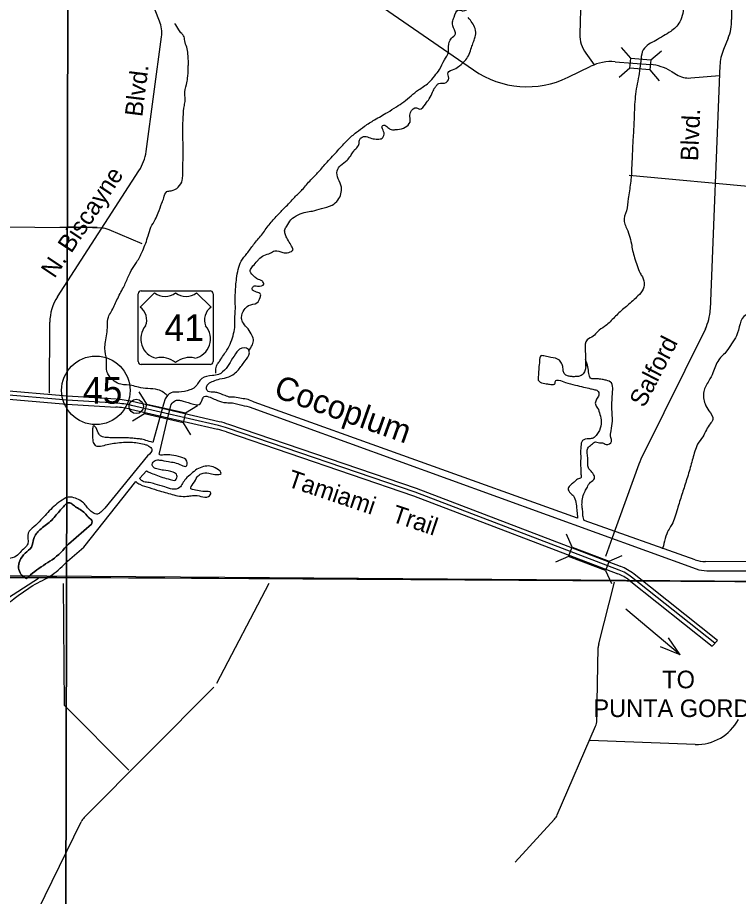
# Model space of a CAD drawing. Extents: x 408847 to 817539, y 923858 to 1151780.
# Drawn here: x 573593 to 592003, y 973182 to 995634 of the extents above; entities that cross this region are included whole.
import ezdxf

# ---------------------------------------------------------------- set-up
doc = ezdxf.new("R2010")
doc.units = 0
for name, color, linetype in [('Adjacent County and State Text', 7, 'Continuous'), ('Bridges', 7, 'Continuous'), ('Cities Incorporated Area', 7, 'Continuous'), ('Cities Incorporated Linear Boundaries', 7, 'Continuous'), ('County Boundary', 7, 'Continuous'), ('Lakes and Ponds', 7, 'Continuous'), ('Level 10', 7, 'Continuous'), ('Level 12', 7, 'Continuous'), ('Level 2', 7, 'Continuous'), ('Level 42', 7, 'Continuous'), ('Level 6', 7, 'Continuous'), ('Local Roads Related Text', 7, 'Continuous'), ('Masks for Road Features', 7, 'Continuous'), ('Narrow River Creek and Branch and Slough', 7, 'Continuous'), ('Other Incorporated Names', 7, 'Continuous'), ('Planning Number US Highways', 7, 'Continuous'), ('Quad Borders', 7, 'Continuous'), ('Roadshields US Highways', 7, 'Continuous'), ('State Roads Related Text', 7, 'Continuous'), ('Town Centers', 7, 'Continuous'), ('US Highways Related Text', 7, 'Continuous'), ('US Routes Highway Center Lines', 7, 'Continuous')]:
    doc.layers.add(name, color=color, linetype=linetype)

msp = doc.modelspace()

# ---------------------------------------------------------------- linework, layer by layer
at = {"layer": 'Adjacent County and State Text'}
msp.add_line((575477, 982694), (574892, 982185), dxfattribs=at)
for points in [[(573818, 981306), (573679, 981416), (573619, 981572), (573648, 981758), (573787, 981950), (573945, 982107), (574004, 982323), (574163, 982547), (574433, 982766), (574664, 983027), (574862, 983240)], [(574862, 983240), (574924, 983236), (575022, 983175), (575127, 983105), (575251, 983022), (575360, 982915), (575408, 982858), (575485, 982788), (575493, 982722), (575477, 982694)], [(574892, 982185), (574475, 981781), (574251, 981640), (573818, 981306)]]:
    msp.add_spline(points, degree=3, dxfattribs=at)
at = {"layer": 'Bridges'}
for p, q in [((589253, 994593), (589018, 994869)), ((589763, 994552), (590039, 994786)), ((589232, 994338), (588956, 994104)), ((589742, 994297), (589977, 994021)), ((576891, 985761), (576699, 986069)), ((577877, 985532), (578184, 985724)), ((576833, 985512), (576526, 985321)), ((577819, 985283), (578010, 984976)), ((587757, 982108), (587609, 982438)), ((587666, 981868), (587335, 981721)), ((588702, 981746), (589033, 981894)), ((588611, 981507), (588758, 981176))]:
    msp.add_line(p, q, dxfattribs=at)
for points in [[(589253, 994593), (589763, 994552), (589742, 994297), (589232, 994338)], [(576891, 985761), (577877, 985532), (577819, 985283), (576833, 985512)], [(587757, 982108), (588702, 981746), (588611, 981507), (587666, 981868)]]:
    msp.add_lwpolyline(points, close=True, dxfattribs=at)
at = {"layer": 'Cities Incorporated Area'}
msp.add_line((573206, 981335), (615530, 981117), dxfattribs=at)
at = {"layer": 'Cities Incorporated Linear Boundaries'}
msp.add_lwpolyline([(567137, 973534), (573183, 973447), (573204, 981332), (576741, 981321), (637423, 980943), (637436, 1005786)], dxfattribs=at)
at = {"layer": 'County Boundary'}
msp.add_line((573205, 981378), (642276, 980861), dxfattribs=at)
at = {"layer": 'Lakes and Ponds'}
for p, q in [((577360, 985897), (577321, 985757)), ((577321, 985757), (577236, 985455)), ((577434, 985413), (577507, 985717)), ((577507, 985717), (577515, 985752)), ((579510, 985689), (590923, 981549)), ((587892, 982842), (579635, 985807)), ((577236, 985455), (577046, 984782)), ((577215, 984506), (577434, 985413)), ((576912, 984439), (575821, 983103)), ((576713, 983866), (576881, 984053)), ((575282, 982106), (576613, 983778)), ((590900, 981781), (588059, 982782)), ((574892, 982185), (575477, 982694)), ((575477, 982694), (574892, 982185)), ((574871, 981748), (575282, 982106)), ((615499, 981594), (591161, 981736)), ((591193, 981501), (615555, 981401))]:
    msp.add_line(p, q, dxfattribs=at)
for centre, start, end in [((591166, 982536), 250.5958, 269.6668), ((591196, 982301), 250.0599, 269.7653)]:
    msp.add_arc(centre, 800, start, end, dxfattribs=at)
for points in [[(579635, 985807), (579479, 985874), (579311, 985905), (579133, 985934), (579037, 985935), (578890, 985976), (578682, 986053), (578574, 986064), (578434, 986105), (578419, 986195), (578469, 986281), (578592, 986346), (578762, 986403), (578987, 986454), (579234, 986638), (579398, 986856), (579512, 987069), (579486, 987156), (579264, 987161), (579196, 987093), (579050, 986872), (578918, 986670), (578725, 986517), (578567, 986486), (578296, 986414), (578119, 986191), (577992, 986123), (577710, 986065), (577511, 986048), (577360, 985897)], [(588100, 986895), (588068, 986584), (587988, 986489), (587889, 986465), (587777, 986460), (587683, 986472), (587598, 986499), (587542, 986563), (587525, 986664), (587499, 986772), (587432, 986878), (587211, 986954), (587067, 986983), (586955, 986990), (586924, 986864), (586904, 986675), (586893, 986499), (586892, 986375), (586936, 986323), (587096, 986280), (587208, 986261), (587298, 986268), (587312, 986278), (587328, 986346), (587411, 986370), (587584, 986313), (587842, 986245), (588050, 986196), (588225, 986153), (588339, 986128), (588421, 986085), (588426, 985959), (588367, 985859), (588351, 985755), (588404, 985659), (588467, 985496), (588500, 985308), (588452, 985088), (588389, 984984), (588295, 984892), (588184, 984873), (588020, 984826), (587979, 984674), (587972, 984554), (587975, 984402), (587970, 984243), (587977, 984103), (587982, 983967), (587985, 983885), (587895, 983845), (587806, 983764), (587716, 983692), (587655, 983604), (587712, 983486), (587788, 983415), (587849, 983253), (587874, 983062), (587890, 982896), (587892, 982842)], [(588059, 982782), (588033, 982909), (588022, 983057), (588008, 983164), (588015, 983300), (588054, 983464), (588085, 983534), (588144, 983639), (588223, 983761), (588329, 983859), (588302, 983961), (588219, 984068), (588161, 984156), (588154, 984254), (588157, 984380), (588159, 984637), (588247, 984726), (588350, 984792), (588494, 984767), (588530, 984769), (588622, 984728), (588762, 984803), (588743, 984906), (588752, 985080), (588786, 985322), (588772, 985634), (588771, 985749), (588780, 985963), (588791, 986121), (588761, 986299), (588627, 986368), (588519, 986391), (588395, 986404), (588227, 986423), (588182, 986537), (588159, 986708), (588100, 986895)], [(577515, 985752), (577628, 985849), (577728, 985857), (577818, 985838), (578088, 985754), (578230, 985749), (578308, 985865), (578359, 985951), (578509, 985934), (578649, 985873), (578858, 985804), (578996, 985795), (579114, 985786), (579252, 985749), (579510, 985689)], [(577046, 984782), (576868, 984832), (576729, 984867), (576675, 984872), (576537, 984888), (576385, 984895), (576211, 984896), (576032, 984896), (575870, 984907), (575729, 984937), (575673, 984990), (575596, 985151), (575536, 985203), (575510, 985125), (575509, 984957), (575516, 984815), (575575, 984704), (575757, 984695), (575921, 984736), (576096, 984765), (576298, 984784), (576524, 984784), (576700, 984763), (576866, 984722), (576947, 984686), (577023, 984607), (576912, 984439)], [(576881, 984053), (576967, 984013), (577122, 983951), (577298, 983886), (577486, 983833), (577622, 983820), (577661, 983938), (577569, 984019), (577317, 984068), (577179, 984095), (577064, 984146), (577030, 984220), (577109, 984320), (577217, 984331), (577443, 984292), (577603, 984265), (577780, 984198), (577900, 984171), (577915, 984303), (577764, 984404), (577522, 984458), (577328, 984461), (577212, 984476), (577215, 984506)], [(576613, 983778), (576716, 983710), (576952, 983626), (577220, 983542), (577405, 983491), (577585, 983438), (577965, 983408), (578087, 983423), (578277, 983402), (578469, 983396), (578532, 983488), (578324, 983526), (578136, 983561), (578014, 983598), (578081, 983727), (578183, 983901), (578281, 983982), (578475, 983999), (578633, 983960), (578791, 983985), (578682, 984108), (578340, 984162), (578174, 984095), (578027, 983978), (577886, 983851), (577807, 983733), (577730, 983627), (577544, 983588), (577352, 983646), (577105, 983715), (576953, 983756), (576819, 983775), (576743, 983826), (576713, 983866)], [(574828, 983368), (574641, 983243), (574329, 982952), (574190, 982799), (574011, 982624), (573864, 982465), (573852, 982192), (573655, 981972), (573514, 981849), (573286, 981763), (573264, 981701), (573256, 981557), (573203, 981488), (572924, 981593), (572674, 981642), (572316, 981519), (572166, 981339), (572213, 981155), (572326, 980964), (572475, 980760), (572554, 980599), (572547, 980536)], [(574862, 983240), (574664, 983027), (574433, 982766), (574163, 982547), (574004, 982323), (573945, 982107), (573787, 981950), (573648, 981758), (573619, 981572), (573679, 981416), (573818, 981306)], [(573818, 981306), (573679, 981416), (573619, 981572), (573648, 981758), (573787, 981950), (573945, 982107), (574004, 982323), (574163, 982547), (574433, 982766), (574664, 983027), (574862, 983240)], [(575821, 983103), (575717, 982995), (575631, 982951), (575525, 982978), (575421, 983063), (575342, 983163), (575251, 983258), (575109, 983339), (574947, 983382), (574828, 983368)], [(575477, 982694), (575493, 982722), (575485, 982788), (575408, 982858), (575360, 982915), (575251, 983022), (575127, 983105), (575022, 983175), (574924, 983236), (574862, 983240)], [(574862, 983240), (574924, 983236), (575022, 983175), (575127, 983105), (575251, 983022), (575360, 982915), (575408, 982858), (575485, 982788), (575493, 982722), (575477, 982694)], [(573818, 981306), (574251, 981640), (574475, 981781), (574892, 982185)], [(574892, 982185), (574475, 981781), (574251, 981640), (573818, 981306)], [(567912, 978885), (568329, 978962), (568739, 978950), (569120, 978879), (569537, 978739), (569871, 978696), (570275, 978881), (570893, 979103), (571420, 979348), (571833, 979689), (572016, 979821), (573025, 980438), (573444, 980744), (573983, 981122), (574472, 981399), (574871, 981748)]]:
    msp.add_spline(points, degree=3, dxfattribs=at)
at = {"layer": 'Level 10'}
msp.add_line((615494, 981067), (573213, 981340), dxfattribs=at)
at = {"layer": 'Level 12'}
for p, q in [((589212, 991608), (593732, 991190)), ((573216, 980725), (574131, 981312)), ((578678, 978626), (580016, 981182)), ((588436, 979635), (588834, 981212)), ((574788, 978058), (574766, 981174)), ((588389, 977681), (588423, 979544)), ((575295, 975194), (578607, 978529)), ((576437, 976403), (574788, 978058)), ((587376, 975265), (588356, 977529)), ((590895, 977065), (588211, 977169)), ((586300, 974054), (587304, 975154)), ((574111, 972825), (575219, 975088))]:
    msp.add_line(p, q, dxfattribs=at)
for centre, radius, start, end in [((588823, 979537), 400, 165.8077, 178.9375), ((587989, 977688), 400, 336.5917, 358.9375), ((590941, 978265), 1200, 267.7972, 332.1984), ((575579, 974913), 400, 135.1954, 153.9033), ((587009, 975424), 400, 317.6167, 336.5918)]:
    msp.add_arc(centre, radius, start, end, dxfattribs=at)
at = {"layer": 'Level 2'}
msp.add_line((615480, 981107), (573213, 981326), dxfattribs=at)
at = {"layer": 'Level 42'}
msp.add_spline([(579493, 987134), (579591, 987273), (579616, 987411), (579559, 987552), (579448, 987719), (579337, 987864), (579314, 987972), (579377, 988168), (579492, 988275), (579705, 988348), (579790, 988482), (579796, 988570), (579697, 988620), (579585, 988701), (579620, 988773), (579718, 988775), (579880, 988824), (579845, 988896), (579717, 988955), (579635, 989021), (579536, 989146), (579573, 989252), (579690, 989384), (579748, 989457), (579883, 989559), (580046, 989618), (580160, 989673), (580368, 989632), (580520, 989633), (580627, 989708), (580591, 989793), (580552, 989863), (580465, 990006), (580427, 990110), (580416, 990214), (580469, 990306), (580572, 990466), (580761, 990595), (580958, 990666), (581122, 990691), (581356, 990755), (581625, 990842), (581774, 990971), (581849, 991135), (581862, 991301), (581784, 991514), (581755, 991720), (581844, 991856), (582007, 991993), (582100, 992103), (582161, 992201), (582228, 992284), (582312, 992392), (582323, 992502), (582366, 992566), (582492, 992595), (582636, 992546), (582788, 992531), (582906, 992554), (582948, 992624), (582927, 992761), (582900, 992863), (582944, 992885), (583052, 992826), (583133, 992773), (583197, 992767), (583237, 992771), (583298, 992774), (583492, 992831), (583615, 992965), (583616, 993067), (583627, 993211), (583784, 993328), (583861, 993296), (584012, 993425), (584107, 993561), (584193, 993728), (584254, 993848), (584296, 993904), (584316, 993934), (584500, 993961), (584605, 994086), (584586, 994231), (584747, 994316), (584880, 994405), (585037, 994552), (585124, 994698), (585187, 994870), (585208, 994930), (585255, 995060), (585289, 995172), (585277, 995352), (585103, 995634)], degree=3, dxfattribs=at)
msp.add_spline([(579493, 987134), (579591, 987273), (579616, 987411), (579559, 987552), (579448, 987719), (579337, 987864), (579314, 987972), (579377, 988168), (579492, 988275), (579705, 988348), (579790, 988482), (579796, 988570), (579697, 988620), (579585, 988701), (579620, 988773), (579718, 988775), (579880, 988824), (579845, 988896), (579717, 988955), (579635, 989021), (579536, 989146), (579573, 989252), (579690, 989384), (579748, 989457), (579883, 989559), (580046, 989618), (580160, 989673), (580368, 989632), (580520, 989633), (580627, 989708), (580591, 989793), (580552, 989863), (580465, 990006), (580427, 990110), (580416, 990214), (580469, 990306), (580572, 990466), (580761, 990595), (580958, 990666), (581122, 990691), (581356, 990755), (581625, 990842), (581774, 990971), (581849, 991135), (581862, 991301), (581784, 991514), (581755, 991720), (581844, 991856), (582007, 991993), (582100, 992103), (582161, 992201), (582228, 992284), (582312, 992392), (582323, 992502), (582366, 992566), (582492, 992595), (582636, 992546), (582788, 992531), (582906, 992554), (582948, 992624), (582927, 992761), (582900, 992863), (582944, 992885), (583052, 992826), (583133, 992773), (583197, 992767), (583237, 992771), (583298, 992774), (583492, 992831), (583615, 992965), (583616, 993067), (583627, 993211), (583784, 993328), (583861, 993296), (584012, 993425), (584107, 993561), (584193, 993728), (584254, 993848), (584296, 993904), (584316, 993934), (584500, 993961), (584605, 994086), (584586, 994231), (584747, 994316), (584880, 994405), (585037, 994552), (585124, 994698), (585187, 994870), (585208, 994930), (585255, 995060), (585289, 995172), (585277, 995352), (585103, 995634)], degree=3, dxfattribs=at)
at = {"layer": 'Level 6'}
for p, q in [((574859, 985960), (563605, 986924)), ((563588, 986725), (574854, 985760)), ((576112, 985884), (574859, 985960)), ((574854, 985760), (576099, 985684)), ((578744, 985309), (576523, 985824)), ((576478, 985629), (578699, 985115)), ((583779, 983599), (578990, 985239)), ((578925, 985050), (583703, 983414)), ((588995, 981612), (583779, 983599)), ((583703, 983414), (588924, 981425)), ((591467, 979721), (589336, 981417)), ((589212, 981260), (591334, 979579)), ((591334, 979579), (591467, 979721))]:
    msp.add_line(p, q, dxfattribs=at)
for centre, radius, start, end in [((575959, 983388), 2300, 76.9617, 86.4971), ((575959, 983388), 2500, 76.9618, 86.4971), ((578180, 982874), 2500, 71.0986, 76.9617), ((578180, 982874), 2300, 71.0986, 76.9617), ((588527, 980397), 1102, 51.5584, 68.8901), ((588526, 980395), 1304, 51.5646, 68.8963)]:
    msp.add_arc(centre, radius, start, end, dxfattribs=at)
at = {"layer": 'Masks for Road Features'}
msp.add_line((574673, 990280), (575626, 990280), dxfattribs=at)
at = {"layer": 'Narrow River Creek and Branch and Slough'}
for p, q in [((574849, 990261), (573215, 990277)), ((575722, 990257), (574876, 990292)), ((576776, 989852), (575930, 990210))]:
    msp.add_line(p, q, dxfattribs=at)
msp.add_arc((575697, 989657), 600, 67.0757, 87.5696, dxfattribs=at)
for points in [[(600169, 1012784), (600058, 1012638), (599920, 1012443), (599719, 1012088), (599450, 1011673), (599276, 1011347), (599058, 1011038), (598896, 1010777), (598739, 1010409), (598657, 1010153), (598647, 1009855), (598678, 1009338), (598785, 1008977), (598903, 1008686), (598947, 1008369), (598905, 1008135), (598771, 1007855), (598593, 1007524), (598441, 1007206), (598417, 1007004), (598483, 1006701), (598554, 1006529), (598534, 1006321), (598389, 1006107), (598209, 1005836), (597997, 1005653), (597777, 1005618), (597548, 1005483), (597478, 1005151), (597508, 1004705), (597499, 1004456), (597478, 1004110), (597477, 1003653), (597501, 1003371), (597506, 1003156), (597390, 1002939), (597285, 1002773), (597271, 1002525), (597245, 1002295), (597200, 1002141), (597119, 1001921), (597021, 1001749), (596899, 1001652), (596587, 1001465), (596394, 1001342), (596219, 1001217), (595523, 1000641), (595291, 1000412), (595060, 1000227), (594814, 1000032), (594679, 999841), (594593, 999511), (594546, 999119), (594524, 998854), (594515, 998169), (594528, 997456), (594514, 997152), (594502, 996870), (594422, 996634), (594317, 996436), (594097, 996133), (593908, 995860), (593793, 995594), (593754, 995166), (593746, 994709), (593725, 994196), (593704, 993810), (593743, 993377), (593920, 992968), (594024, 992602), (594067, 992266), (593924, 991872), (593854, 991542), (593700, 990982), (593552, 990640), (593421, 990281), (593362, 990075), (593242, 989855), (593098, 989654), (592947, 989424), (592821, 989113), (592715, 988849), (592593, 988597), (592471, 988344), (592389, 988122), (592197, 988037), (591955, 987504), (591829, 987302), (591702, 987111), (591500, 986888), (591352, 986562), (591246, 986352), (591118, 986081), (591150, 985764), (591249, 985589), (591351, 985364), (591277, 985259)], [(590739, 997053), (590710, 996823), (590659, 996505), (590630, 996254), (590612, 995968), (590584, 995740), (590504, 995528), (590397, 995381), (590273, 995279), (590086, 995164), (589891, 995049), (589718, 994952), (589571, 994811), (589515, 994581), (589484, 994339), (589446, 994079), (589394, 993811), (589346, 993284), (589334, 992956), (589309, 992519), (589290, 992107), (589276, 991786), (589247, 991404), (589188, 991008), (589140, 990698), (589084, 990423), (589131, 990291), (589268, 989856), (589301, 989685), (589414, 989302), (589495, 989105), (589550, 989009), (589589, 988906), (589566, 988698), (589435, 988523), (589173, 988282), (589042, 988172), (588808, 987948), (588581, 987739), (588410, 987616), (588297, 987496), (588138, 987401), (588088, 987161), (588101, 986934), (588095, 986718)], [(578655, 986548), (578656, 986662), (578699, 986784), (578762, 986868), (578853, 987013), (578940, 987137), (579041, 987345), (579109, 987561), (579140, 987769), (579137, 987919), (579157, 988205), (579152, 988337), (579156, 988608), (579185, 988968), (579228, 989202), (579304, 989412), (579449, 989605), (579619, 989835), (579819, 990078), (580019, 990343), (580221, 990578), (580420, 990779), (580670, 991044), (580864, 991241), (581081, 991488), (581281, 991695), (581497, 991942), (581769, 992235), (582025, 992508), (582246, 992705), (582452, 992856), (582711, 993022), (583040, 993213), (583266, 993353), (583455, 993482), (583646, 993638), (583831, 993785), (584088, 993969), (584246, 994145), (584369, 994310), (584493, 994552), (584596, 994751), (584599, 994895), (584671, 995105), (584773, 995217), (584748, 995323), (584704, 995524), (584742, 995646), (584854, 995829), (584974, 995805), (585132, 995907)], [(577407, 985989), (577321, 986055), (577176, 986128), (576918, 986154), (576678, 986189), (576514, 986233), (576230, 986266), (575932, 986480), (575876, 986591), (575860, 986890), (575822, 987182), (575840, 987350), (575889, 987761), (575912, 987977), (575983, 988115), (576129, 988420), (576296, 988742), (576418, 989007), (576527, 989223), (576659, 989426), (576789, 989682), (576927, 990062), (576997, 990277), (577110, 990475), (577183, 990643), (577279, 990897), (577326, 991025), (577405, 991188), (577514, 991210), (577696, 991303), (577800, 991480), (577809, 991616), (577815, 991927), (577825, 992187), (577818, 992432), (577811, 992768), (577825, 993090), (577853, 993391), (577874, 993523), (577861, 993675), (577903, 993923), (577936, 994089), (577950, 994333), (577955, 994462), (577942, 994710), (577912, 994876), (577863, 995041), (577834, 995167), (577784, 995224), (577709, 995322), (577612, 995487)], [(591277, 985259), (591184, 985101), (591090, 984925), (590961, 984734), (590888, 984554), (590787, 984184), (590670, 983800), (590558, 983446), (590443, 983083), (590304, 982687), (590152, 982389), (590058, 982083), (590058, 982085)]]:
    msp.add_spline(points, degree=3, dxfattribs=at)
at = {"layer": 'Other Incorporated Names'}
for p, q in [((588057, 999550), (587954, 995209)), ((577221, 995542), (576405, 997625)), ((581565, 996839), (585238, 994295)), ((591807, 996701), (591829, 995587)), ((576875, 992212), (577269, 995143)), ((591739, 995105), (591620, 994817)), ((588106, 994722), (588320, 994425)), ((588852, 994506), (589753, 994434)), ((587651, 994108), (588233, 994390)), ((590281, 994263), (590422, 994177)), ((591530, 994406), (591282, 988172)), ((590783, 994092), (591520, 994152)), ((574610, 988503), (576693, 991720)), ((574411, 986042), (574417, 987855)), ((591158, 987686), (589566, 984475)), ((589458, 984222), (588781, 982342)), ((588781, 982342), (588611, 981868))]:
    msp.add_line(p, q, dxfattribs=at)
for centre, radius, start, end in [((590630, 995563), 1200, 337.5328, 1.139), ((576476, 995250), 800, 352.354, 21.3788), ((588754, 995190), 800, 178.6434, 215.8474), ((592729, 994359), 1200, 157.5328, 177.7301), ((588756, 993310), 1200, 85.4198, 115.8406), ((589657, 993238), 1200, 58.7017, 85.4197), ((586605, 996268), 2400, 235.2877, 295.8406), ((590734, 994690), 600, 238.7016, 274.6967), ((575686, 992372), 1200, 327.0747, 352.354), ((575617, 987851), 1200, 147.0747, 179.7935), ((590083, 988219), 1200, 333.626, 357.7301), ((591716, 983408), 2400, 153.626, 160.1893)]:
    msp.add_arc(centre, radius, start, end, dxfattribs=at)
at = {"layer": 'Planning Number US Highways'}
msp.add_circle((575591, 986111), 875, dxfattribs=at)
at = {"layer": 'Quad Borders'}
for p, q in [((574822, 969374), (574913, 1014812)), ((574913, 1014812), (574822, 969374))]:
    msp.add_line(p, q, dxfattribs=at)
at = {"layer": 'Roadshields US Highways'}
for p, q in [((577092, 988604), (576722, 988238)), ((576747, 988654), (578509, 988654)), ((577092, 988604), (577092, 988604)), ((577628, 988602), (577628, 988602)), ((578534, 988238), (578164, 988604)), ((576672, 986845), (576672, 988579)), ((578584, 988579), (578584, 986845)), ((578509, 986770), (576747, 986770))]:
    msp.add_line(p, q, dxfattribs=at)
for centre, radius, start, end in [((576747, 988579), 75, 90, 180), ((577361, 988939), 430, 231.2915, 308.3626), ((577895, 988939), 430, 231.6374, 308.7085), ((578509, 988579), 75, 0, 90), ((576481, 987908), 409, 338.3056, 53.8199), ((578775, 987908), 409, 126.1801, 201.6944), ((577238, 987426), 501, 138.7831, 258.2378), ((578018, 987426), 501, 281.7622, 41.2169), ((576747, 986845), 75, 180, 270), ((577268, 986393), 558, 49.9101, 103.7765), ((577987, 986393), 558, 76.2235, 130.0899), ((578509, 986845), 75, 270, 0)]:
    msp.add_arc(centre, radius, start, end, dxfattribs=at)
at = {"layer": 'Town Centers'}
msp.add_circle((576623, 985699), 184, dxfattribs=at)
at = {"layer": 'US Highways Related Text'}
for q in [(589125, 980522), (590221, 979787), (590013, 979554)]:
    msp.add_line((590512, 979356), q, dxfattribs=at)
at = {"layer": 'US Routes Highway Center Lines'}
for p, q in [((574857, 985860), (563597, 986825)), ((576106, 985784), (574857, 985860)), ((578721, 985212), (576500, 985726)), ((583743, 983506), (578957, 985145)), ((588960, 981518), (583743, 983506)), ((591400, 979654), (589274, 981338))]:
    msp.add_line(p, q, dxfattribs=at)
for centre, radius, start, end in [((575959, 983388), 2400, 76.9618, 86.4971), ((578180, 982874), 2400, 71.0986, 76.9617), ((588528, 980399), 1200, 51.5396, 68.8714)]:
    msp.add_arc(centre, radius, start, end, dxfattribs=at)

# ---------------------------------------------------------------- texts
at = {"layer": 'Level 42'}
msp.add_text('Cocoplum', height=600, rotation=340.4632, dxfattribs=at).set_placement((580105, 985954))
at = {"layer": 'Local Roads Related Text'}
for s, rotation, p in [('Blvd.', 82.9164, (576776, 993085)), ('Blvd.', 87.5281, (590971, 991962)), ('N. Biscayne', 56.3097, (574535, 988954)), ('Salford', 62.8186, (589597, 985648))]:
    msp.add_text(s, height=450, rotation=rotation, dxfattribs=at).set_placement(p)
at = {"layer": 'Planning Number US Highways'}
msp.add_text('45', height=680, dxfattribs=at).set_placement((575257, 985771))
at = {"layer": 'Roadshields US Highways'}
msp.add_text('41', height=680, dxfattribs=at).set_placement((577342, 987371))
at = {"layer": 'State Roads Related Text'}
msp.add_text('Tamiami   Trail', height=450, rotation=341.3822, dxfattribs=at).set_placement((580458, 983664))
at = {"layer": 'US Highways Related Text'}
for s, p in [('TO', (590057, 978499)), ('PUNTA GORDA', (588299, 977764))]:
    msp.add_text(s, height=450, rotation=359.9999, dxfattribs=at).set_placement(p)

doc.saveas('drawing.dxf')
